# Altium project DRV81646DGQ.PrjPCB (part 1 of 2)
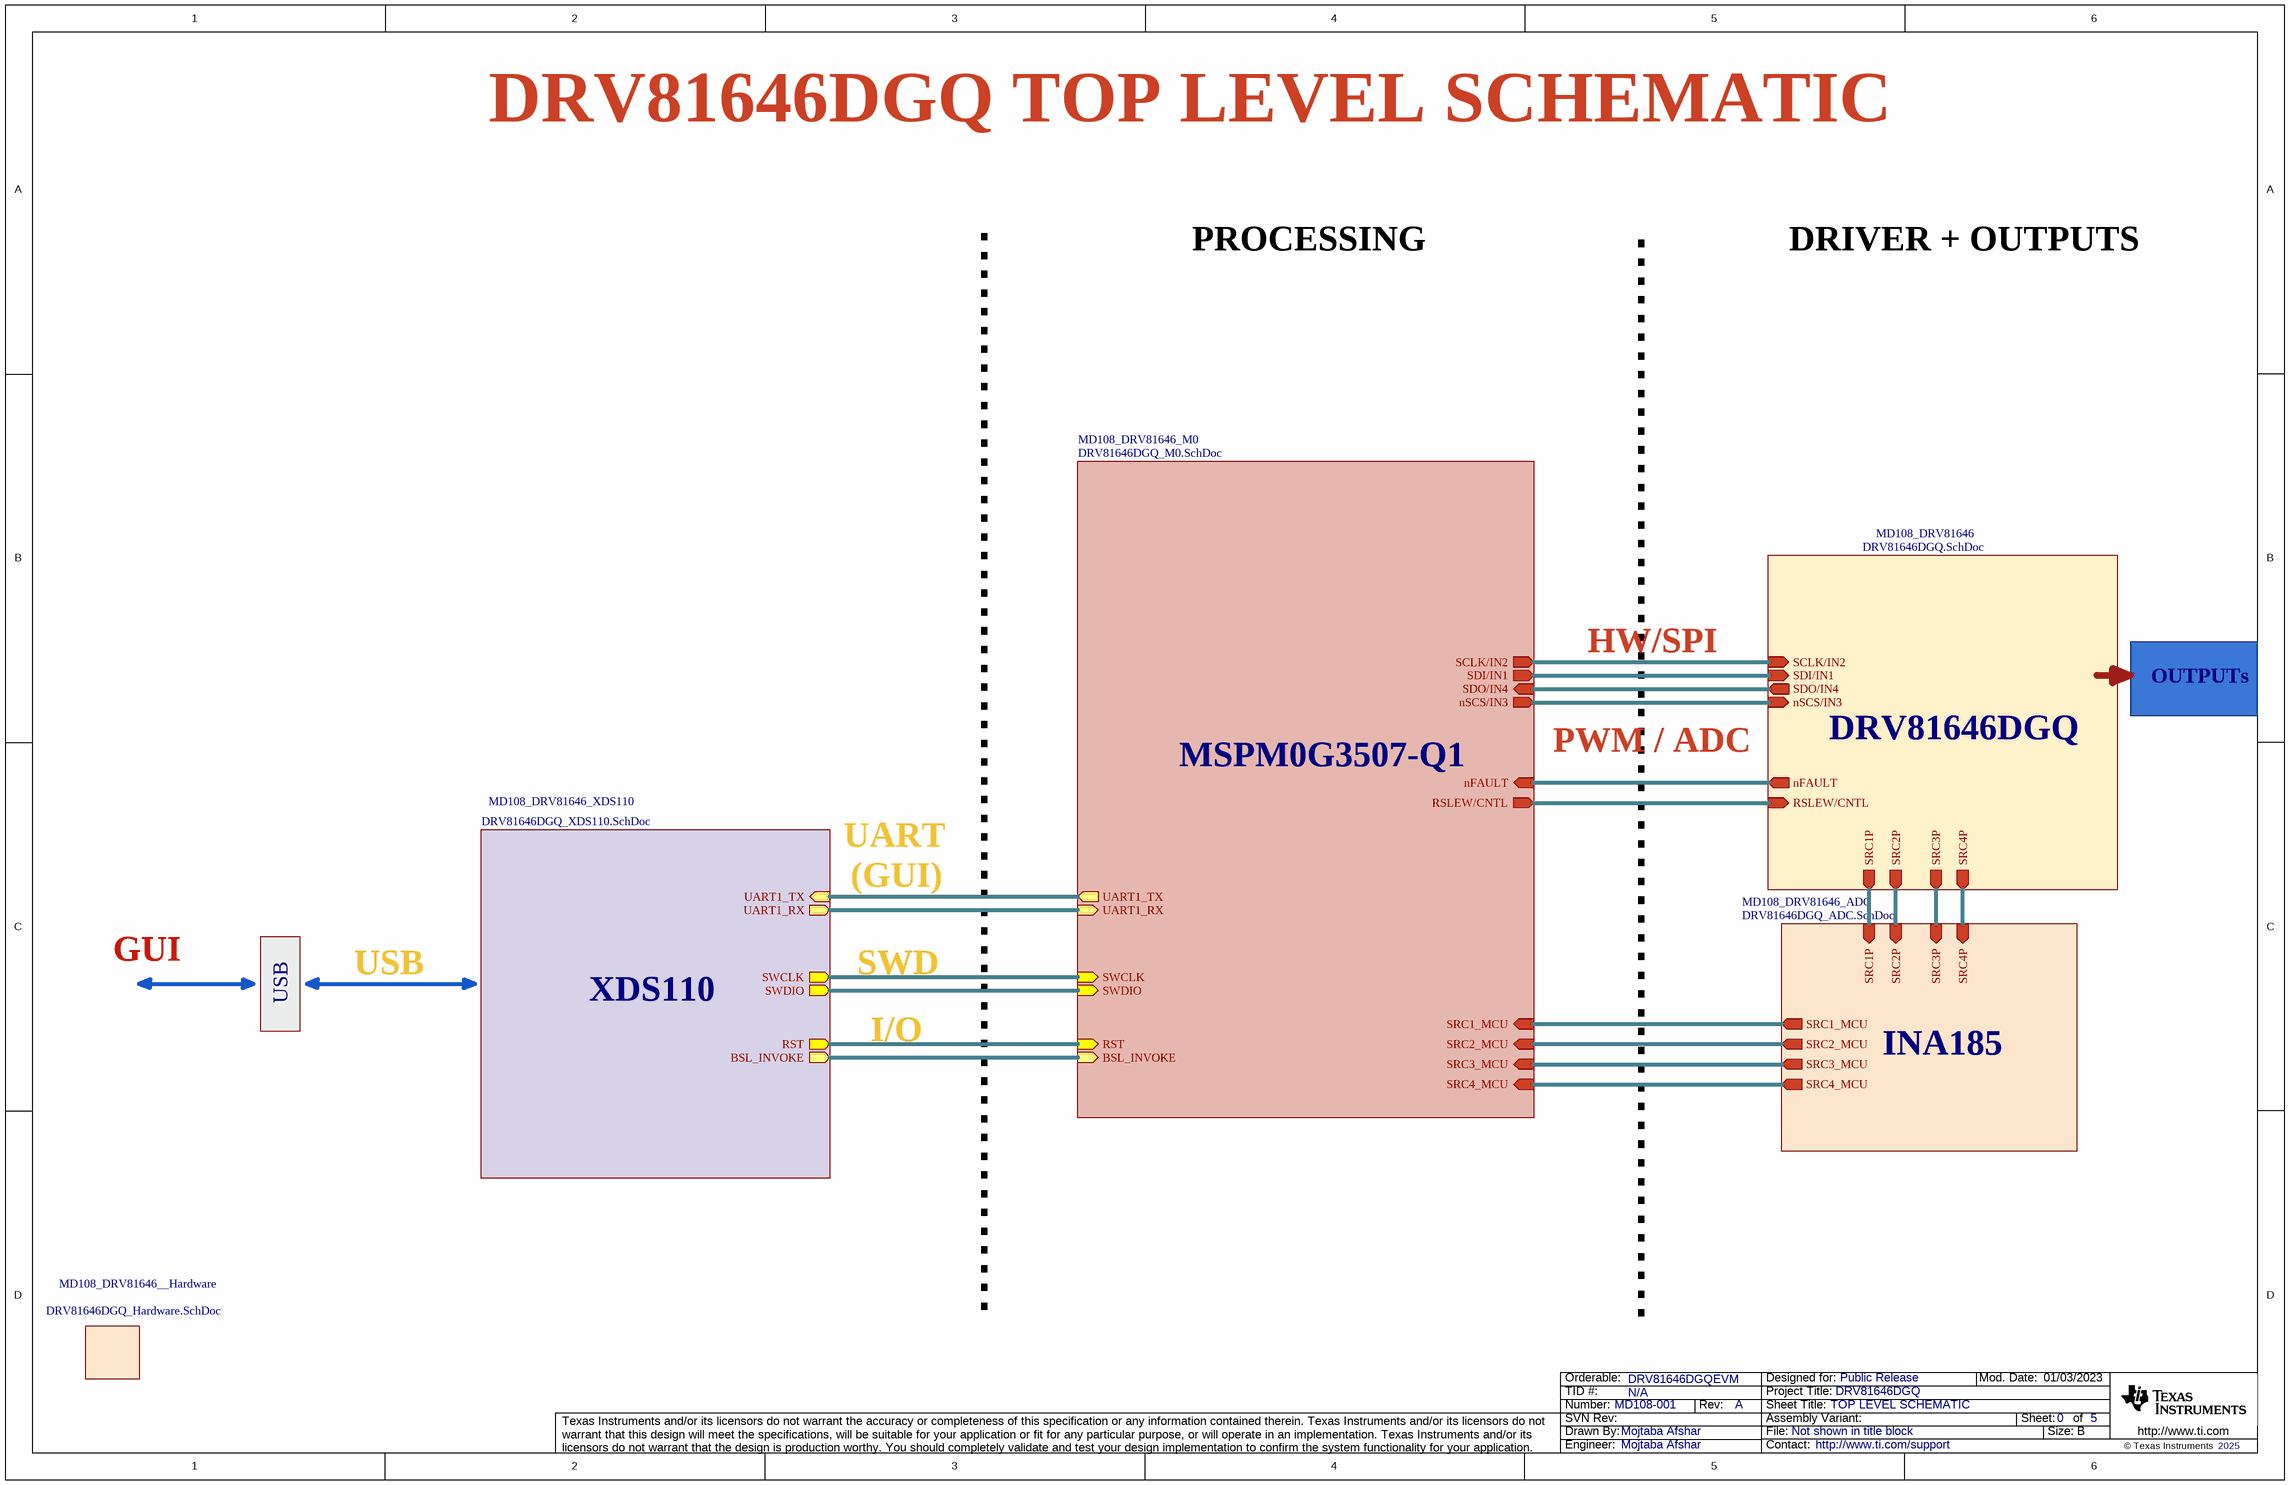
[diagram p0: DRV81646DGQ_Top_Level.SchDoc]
CopyrightYear: 2025; EVM_Orderable: DRV81646DGQEVM; PCB_Layout: Mojtaba Afshar; PCB_Rev: A; PRJ_Customer: Public Release; PRJ_Engineer: Mojtaba Afshar; PRJ_Number: MD108-001; PRJ_Title: DRV81646DGQ; SCH_Rev: A; TechSupport: http://www.ti.com/support; TID: N/A
6 sheets, 256 parts. Net scope: hierarchical (ports join the sheet entries above them; power ports are global).
Board file: MD108_DRV81646DGQ.PcbDoc
Sheets:
  DRV81646DGQ_Top_Level.SchDoc
    MD108_DRV81646__Hardware = DRV81646DGQ_Hardware.SchDoc
    MD108_DRV81646_XDS110 = DRV81646DGQ_XDS110.SchDoc
    MD108_DRV81646_M0 = DRV81646DGQ_M0.SchDoc
    MD108_DRV81646 = DRV81646DGQ.SchDoc
    MD108_DRV81646_ADC = DRV81646DGQ_ADC.SchDoc

## Sheet DRV81646DGQ_Top_Level.SchDoc: TOP LEVEL SCHEMATIC
size 431 x 279 mm; Date: Not shown in title block; ApprovedBy: Not shown in title block; CheckedBy: Not shown in title block; Author: Not shown in title block; CompanyName: Not shown in title block; DrawnBy: Mojtaba Afshar; Engineer: Not shown in title block; Organization: Not shown in title block; Address1: Not shown in title block; Address2: Not shown in title block; Address3: Not shown in title block; Address4: Not shown in title block; DocumentNumber: 2; Revision: Use project parameter SCH_Rev; SheetNumber: 0; SheetTotal: 5; PageSetup: Record=PageOptions¦CenterHorizontal=True¦CenterVertical=True¦PrintScale=1.00¦XCorrection=1.00¦YCorrection=1.00¦PrintKind=0¦BorderSize=5000000¦LeftOffset=0¦BottomOffset=0¦Orientation=2¦PaperLength=1000¦PaperWidth=1000¦Scale=100¦PaperSource=15¦PrintQuality=600¦MediaType=1¦DitherType=10¦PaperKind=Letter¦PrintScaleMode=1

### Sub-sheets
MD108_DRV81646 = DRV81646DGQ.SchDoc: nFAULT (out), SDI/IN1 (in), SDO/IN4 (out), SCLK/IN2 (in), nSCS/IN3 (in), RSLEW/CNTL (in), SRC1P (out), SRC2P (out), SRC3P (out), SRC4P (out)
MD108_DRV81646__Hardware = DRV81646DGQ_Hardware.SchDoc: no entries
MD108_DRV81646_ADC = DRV81646DGQ_ADC.SchDoc: SRC1P (in), SRC2P (in), SRC3P (in), SRC4P (in), SRC1_MCU (out), SRC2_MCU (out), SRC3_MCU (out), SRC4_MCU (out)
MD108_DRV81646_M0 = DRV81646DGQ_M0.SchDoc: SWDIO (in), SWCLK (in), nFAULT (in), SDI/IN1 (out), SDO/IN4 (in), SCLK/IN2 (out), RST (in), nSCS/IN3 (out), UART1_TX (out), UART1_RX (in), BSL_INVOKE (in), RSLEW/CNTL (out), SRC1_MCU (in), SRC2_MCU (in), SRC3_MCU (in), SRC4_MCU (in)
MD108_DRV81646_XDS110 = DRV81646DGQ_XDS110.SchDoc: SWDIO (out), SWCLK (out), RST (out), UART1_RX (out), UART1_TX (in), BSL_INVOKE (out)

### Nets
BSL_INVOKE: sheet MD108_DRV81646_XDS110/BSL_INVOKE, sheet MD108_DRV81646_M0/BSL_INVOKE
nFAULT: sheet MD108_DRV81646_M0/nFAULT, sheet MD108_DRV81646/nFAULT
nSCS/IN3: sheet MD108_DRV81646_M0/nSCS/IN3, sheet MD108_DRV81646/nSCS/IN3
RSLEW/CNTL: sheet MD108_DRV81646_M0/RSLEW/CNTL, sheet MD108_DRV81646/RSLEW/CNTL
RST: sheet MD108_DRV81646_XDS110/RST, sheet MD108_DRV81646_M0/RST
SCLK/IN2: sheet MD108_DRV81646_M0/SCLK/IN2, sheet MD108_DRV81646/SCLK/IN2
SDI/IN1: sheet MD108_DRV81646_M0/SDI/IN1, sheet MD108_DRV81646/SDI/IN1
SDO/IN4: sheet MD108_DRV81646_M0/SDO/IN4, sheet MD108_DRV81646/SDO/IN4
SRC1: sheet MD108_DRV81646/SRC1P, sheet MD108_DRV81646_ADC/SRC1P
SRC1_ADC_MCU: sheet MD108_DRV81646_M0/SRC1_MCU, sheet MD108_DRV81646_ADC/SRC1_MCU
SRC2: sheet MD108_DRV81646/SRC2P, sheet MD108_DRV81646_ADC/SRC2P
SRC2_ADC_MCU: sheet MD108_DRV81646_M0/SRC2_MCU, sheet MD108_DRV81646_ADC/SRC2_MCU
SRC3: sheet MD108_DRV81646/SRC3P, sheet MD108_DRV81646_ADC/SRC3P
SRC3_ADC_MCU: sheet MD108_DRV81646_M0/SRC3_MCU, sheet MD108_DRV81646_ADC/SRC3_MCU
SRC4: sheet MD108_DRV81646/SRC4P, sheet MD108_DRV81646_ADC/SRC4P
SRC4_ADC_MCU: sheet MD108_DRV81646_M0/SRC4_MCU, sheet MD108_DRV81646_ADC/SRC4_MCU
SWCLK: sheet MD108_DRV81646_XDS110/SWCLK, sheet MD108_DRV81646_M0/SWCLK
SWDIO: sheet MD108_DRV81646_XDS110/SWDIO, sheet MD108_DRV81646_M0/SWDIO
UART1_RX: sheet MD108_DRV81646_XDS110/UART1_RX, sheet MD108_DRV81646_M0/UART1_RX
UART1_TX: sheet MD108_DRV81646_XDS110/UART1_TX, sheet MD108_DRV81646_M0/UART1_TX

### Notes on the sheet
- DRV81646DGQ TOP LEVEL SCHEMATIC
- PROCESSING
- DRIVER + OUTPUTS
- HW/SPI
- OUTPUTs
- PWM / ADC
- DRV81646DGQ
- MSPM0G3507-Q1
- UART
- (GUI)
- GUI
- USB
- XDS110
- SWD
- I/O
- INA185

## Sheet DRV81646DGQ_Hardware.SchDoc: HARDWARE
size 431 x 279 mm; Date: Not shown in title block; ApprovedBy: Not shown in title block; CheckedBy: Not shown in title block; Author: Not shown in title block; CompanyName: Not shown in title block; DrawnBy: Mojtaba Afshar; Engineer: Not shown in title block; Organization: Not shown in title block; Address1: Not shown in title block; Address2: Not shown in title block; Address3: Not shown in title block; Address4: Not shown in title block; DocumentNumber: 3; Revision: Use project parameter SCH_Rev; SheetNumber: 5; SheetTotal: 5; PageSetup: Record=PageOptions¦CenterHorizontal=True¦CenterVertical=True¦PrintScale=1.00¦XCorrection=1.00¦YCorrection=1.00¦PrintKind=0¦BorderSize=5000000¦LeftOffset=0¦BottomOffset=0¦Orientation=2¦PaperLength=1000¦PaperWidth=1000¦Scale=100¦PaperSource=15¦PrintQuality=600¦MediaType=1¦DitherType=10¦PaperKind=Letter¦PrintScaleMode=1
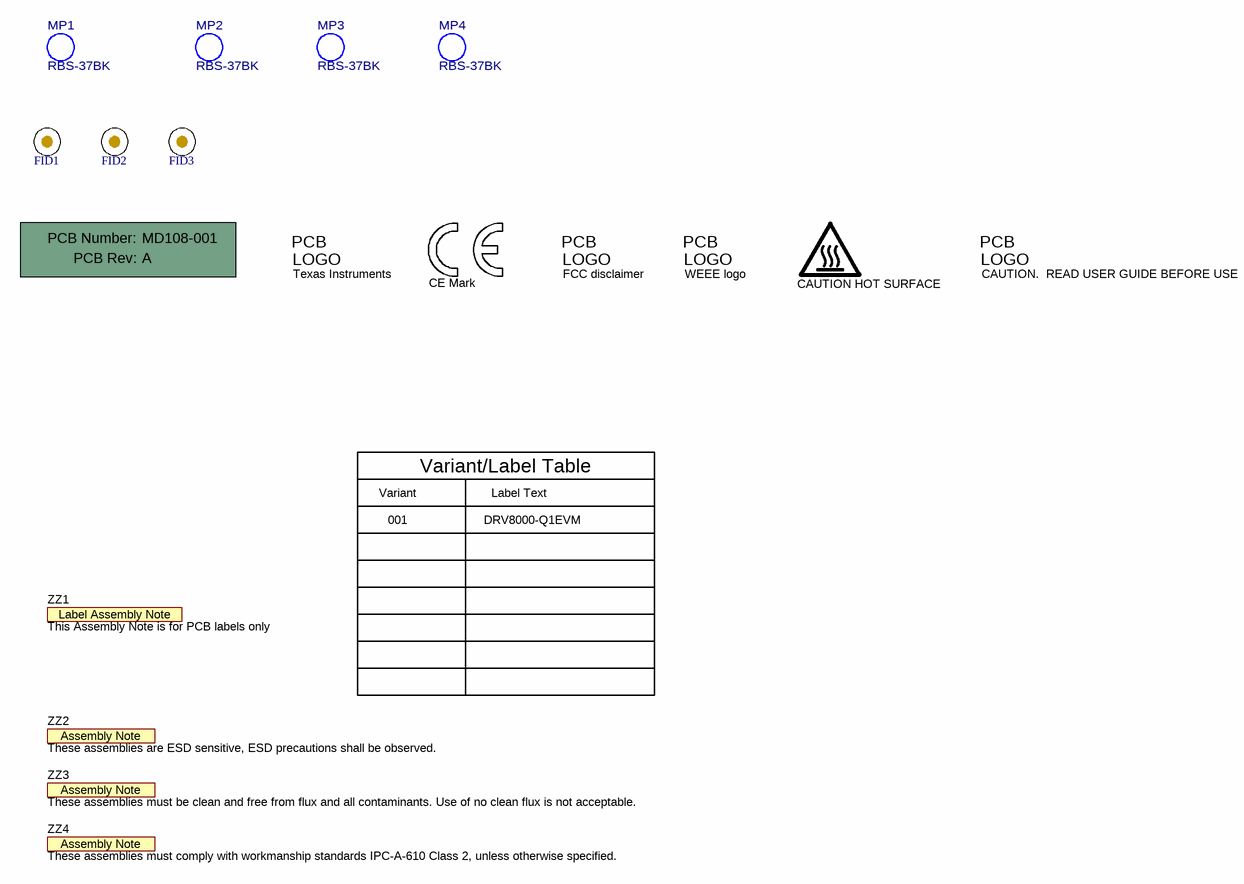
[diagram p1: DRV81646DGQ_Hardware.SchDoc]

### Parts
!PCB1  Printed Circuit Board  (value not drawn)  (mechanical)
FID1  Fiducial  [Fiducial10-20]  (value not drawn)
FID2  Fiducial  [Fiducial10-20]  (value not drawn)
FID3  Fiducial  [Fiducial10-20]  (value not drawn)
Logo1  CE Mark  [CE_Mark_5mm]  (no BOM)
Logo2  Texas Instruments  [TI_Stacked_Overlay_Small]  (no BOM)
Logo3  FCC disclaimer  [FCC_disclaimer]  (no BOM)
Logo4  WEEE logo  [WEEE_Minimum]  (no BOM)
LOGO5  CAUTION HOT SURFACE  [IEC_HotSurface_Small]  (no BOM)
Logo6  CAUTION.  READ USER GUIDE BEFORE USE  [IEC_Caution_Small]  (no BOM)
MP1  RBS-37BK  [FP-RBS-37BK_BUMPER_CYLI-MFG]
MP2  RBS-37BK  [FP-RBS-37BK_BUMPER_CYLI-MFG]
MP3  RBS-37BK  [FP-RBS-37BK_BUMPER_CYLI-MFG]
MP4  RBS-37BK  [FP-RBS-37BK_BUMPER_CYLI-MFG]
ZZ1  This Assembly Note is for PCB labels only  [AssemblyNoteLabel]  (no BOM)
ZZ2  These assemblies are ESD sensitive, ESD precautions shall be observed.  [AssemblyNote]  (no BOM)
ZZ3  These assemblies must be clean and free from flux and all contaminants. Use of no clean flux is not acceptable.  [AssemblyNote]  (no BOM)
ZZ4  These assemblies must comply with workmanship standards IPC-A-610 Class 2, unless otherwise specified.  [AssemblyNote]  (no BOM)

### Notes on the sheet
- Variant
- Variant/Label Table
- Label Text
- 001
- DRV8000-Q1EVM

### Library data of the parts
!PCB1 = CMP-0003618-2: Manufacturer: Any; PartNumber: MD108-001
FID1-FID3 = CMP-0077181-1: Fiducial mark.  There is nothing to buy or mount.
Logo1 = CMP-0074844-2: Manufacturer: Texas Instruments; SymbolCreator: a0412235; AEC Category: Q200; CompType: IC
Logo2 = CMP-0074838-1: Texas Instrument Corporate Signature; SymbolCreator: a0412235; Lib Reference: TI_Logo
Logo3 = CMP-0074847-1: FCC_disclaimer
Logo4 = CMP-0074769-4: Manufacturer: Texas Instruments; AEC Category: Q200; CompType: IC
LOGO5 = CMP-0074837-2: IEC 61010-1 Hot Surface Warning; Manufacturer: Texas Instruments; SymbolCreator: a0412235; CompType: IC; AEC Category: Q200
Logo6 = CMP-0074836-1: IEC 61010-1 Caution Warning; SymbolCreator: a0412235; Lib Reference: IEC_Caution
MP1-MP4 = CMP-0122650-1: Bumper Cylindrical, Dome 0.720" Dia (18.30mm) Polyurethane Black; Manufacturer: Essentra Components; AEC Qualified: No; SizeZ_mm: 14.7mm
ZZ1 = CMP-0003616-3
ZZ2 = CMP-0077236-1
ZZ3 = CMP-0077237-1
ZZ4 = CMP-0077238-1

## Sheet DRV81646DGQ_XDS110.SchDoc: XDS110
size 431 x 279 mm; Date: Not shown in title block; ApprovedBy: Not shown in title block; CheckedBy: Not shown in title block; Author: Not shown in title block; CompanyName: Not shown in title block; DrawnBy: Mojtaba Afshar; Engineer: Not shown in title block; Organization: Not shown in title block; Address1: Not shown in title block; Address2: Not shown in title block; Address3: Not shown in title block; Address4: Not shown in title block; DocumentNumber: 2; Revision: Use project parameter SCH_Rev; SheetNumber: 1; SheetTotal: 5; PageSetup: Record=PageOptions¦CenterHorizontal=True¦CenterVertical=True¦PrintScale=1.00¦XCorrection=1.00¦YCorrection=1.00¦PrintKind=0¦BorderSize=5000000¦LeftOffset=0¦BottomOffset=0¦Orientation=2¦PaperLength=1000¦PaperWidth=1000¦Scale=100¦PaperSource=15¦PrintQuality=600¦MediaType=1¦DitherType=10¦PaperKind=Letter¦PrintScaleMode=1
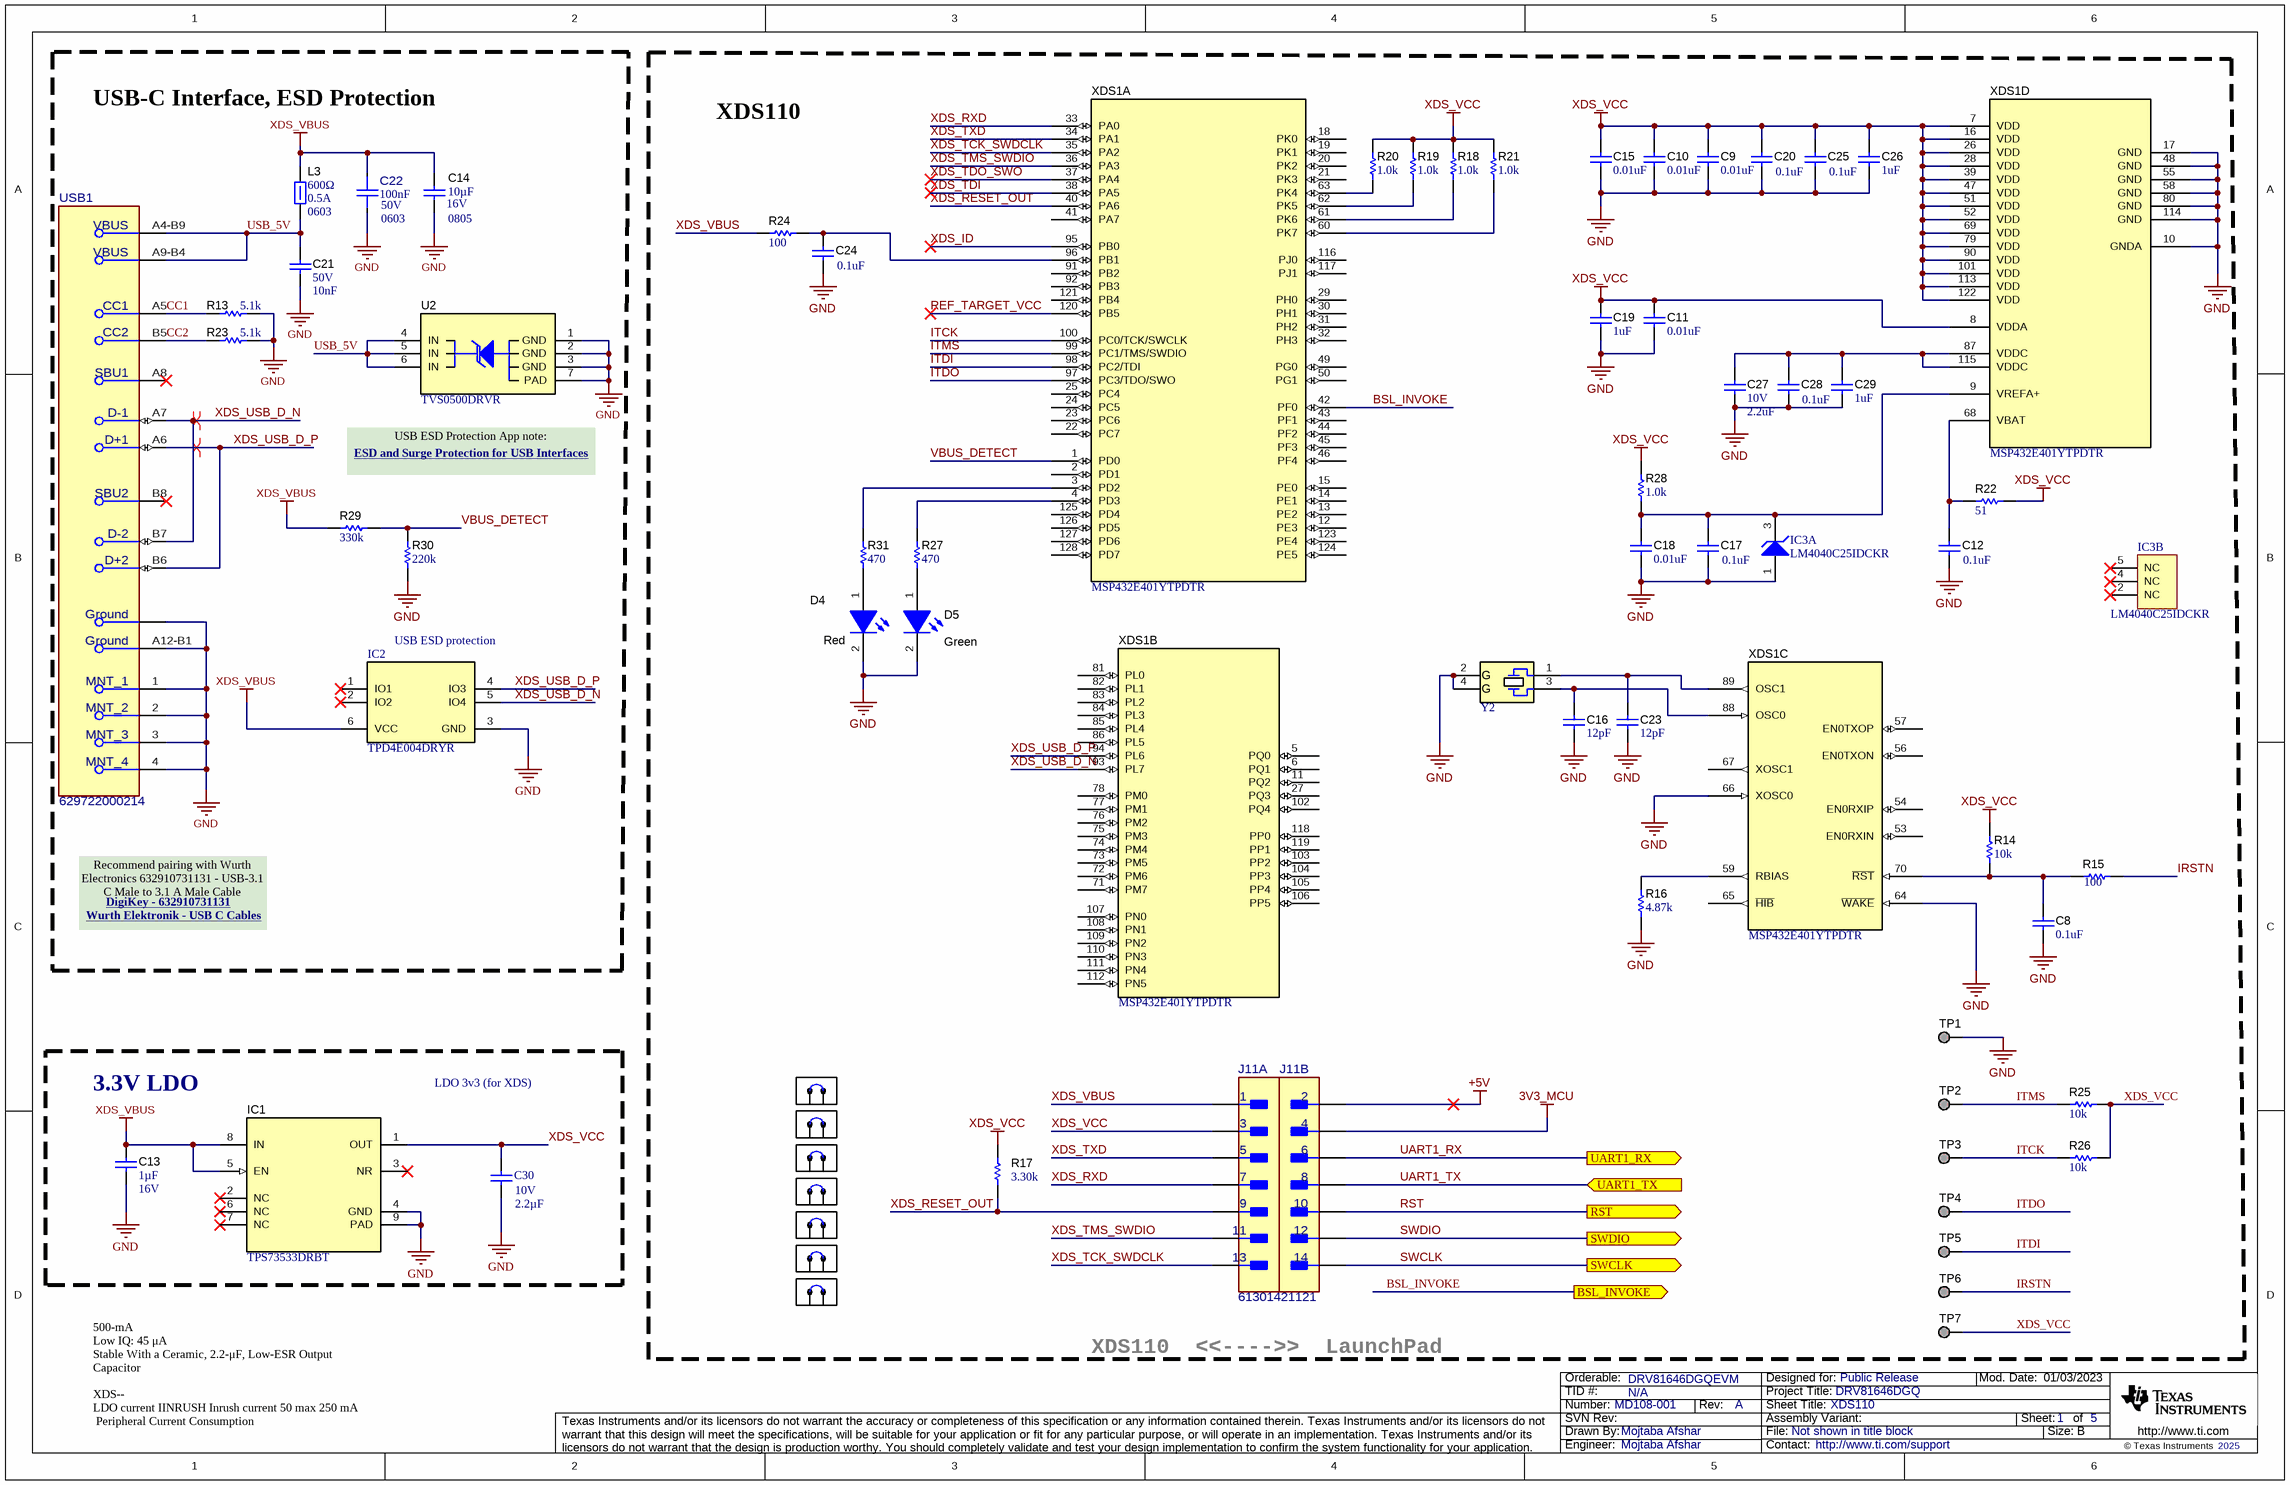
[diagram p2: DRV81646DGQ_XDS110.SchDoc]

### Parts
C8  ValueDisplayed: 0.1uF  [0402]  (hidden comment: GRM155R70J104KA01D)
C9  ValueDisplayed: 0.01uF  [0402]  (hidden comment: GRM155R71E103KA01D)
C10  ValueDisplayed: 0.01uF  [0402]  (hidden comment: GRM155R71E103KA01D)
C11  ValueDisplayed: 0.01uF  [0402]  (hidden comment: GRM155R71E103KA01D)
C12  ValueDisplayed: 0.1uF  [0402]  (hidden comment: GRM155R70J104KA01D)
C13  Cap_F: 1µF  VDC_V: 16V  [0603]  (hidden comment: 885012206052)
C14  PackageReference: 0805  VDC_V: 16V  ValueDisplayed: 10µF  [0805_150]  (hidden comment: 885012107014)
C15  ValueDisplayed: 0.01uF  [0402]  (hidden comment: GRM155R71E103KA01D)
C16  ValueDisplayed: 12pF  [0402]  (hidden comment: GRM1555C1H120JA01D)
C17  ValueDisplayed: 0.1uF  [0402]  (hidden comment: GRM155R70J104KA01D)
C18  ValueDisplayed: 0.01uF  [0402]  (hidden comment: GRM155R71E103KA01D)
C19  ValueDisplayed: 1uF  [0402]  (hidden comment: C1005X5R1E105K050BC)
C20  ValueDisplayed: 0.1uF  [0402]  (hidden comment: GRM155R70J104KA01D)
C21  VDC_V: 50V  Cap_F: 10nF  [0603]  (hidden comment: 885012206089)
C22  Cap_F: 100nF  PackageReference: 0603  VDC_V: 50V  [FP-885012206095_0603-MFG]  (hidden comment: 885012206095)
C23  ValueDisplayed: 12pF  [0402]  (hidden comment: GRM1555C1H120JA01D)
C24  ValueDisplayed: 0.1uF  [0402]  (hidden comment: GRM155R70J104KA01D)
C25  ValueDisplayed: 0.1uF  [0402]  (hidden comment: GRM155R70J104KA01D)
C26  ValueDisplayed: 1uF  [0402]  (hidden comment: C1005X5R1E105K050BC)
C27  VDC_V: 10V  ValueDisplayed: 2.2uF  [0603]  (hidden comment: C0603C225K8PACTU)
C28  ValueDisplayed: 0.1uF  [0402]  (hidden comment: GRM155R70J104KA01D)
C29  ValueDisplayed: 1uF  [0402]  (hidden comment: C1005X5R1E105K050BC)
C30  Cap_F: 2.2µF  Rated Voltage (DC): 10V  [WCAP-CSGP_0603_L1.6W0.8H0.8_Reflow]  (hidden comment: 885012206027)
D4  value Red  [LED_LTST-C190_Red]  (hidden comment: LTST-C190KRKT)
D5  value Green  [LED_LTST-C190]  (hidden comment: LTST-C190GKT)
IC1  TPS73533DRBT  [DRB0008A]
IC2  TPD4E004DRYR  [DRY0006A]
IC3  LM4040C25IDCKR  [DCK0005A_N]  (parts A,B of 2)
J11  61301421121  [FP-61301421121_HDR14-MFG]  (parts A,B of 2)
L3  Value2: 0.5A  ValueDisplayed: 600Ω  [0603]  (hidden comment: 742863160)
R13  ValueDisplayed: 5.1k  [0603]  (hidden comment: RC0603JR-075K1L)
R14  ValueDisplayed: 10k  [0402]  (hidden comment: CRCW040210K0JNED)
R15  ValueDisplayed: 100  [0402]  (hidden comment: CRCW0402100RJNED)
R16  ValueDisplayed: 4.87k  [0402]  (hidden comment: CRCW04024K87FKED)
R17  ValueDisplayed: 3.30k  [0402]  (hidden comment: ERJ-2RKF3301X)
R18  ValueDisplayed: 1.0k  [0402]  (hidden comment: CRCW04021K00JNED)
R19  ValueDisplayed: 1.0k  [0402]  (hidden comment: CRCW04021K00JNED)
R20  ValueDisplayed: 1.0k  [0402]  (hidden comment: CRCW04021K00JNED)
R21  ValueDisplayed: 1.0k  [0402]  (hidden comment: CRCW04021K00JNED)
R22  ValueDisplayed: 51  [0402]  (hidden comment: CRCW040251R0JNED)
R23  ValueDisplayed: 5.1k  [0603]  (hidden comment: RC0603JR-075K1L)
R24  ValueDisplayed: 100  [0402]  (hidden comment: CRCW0402100RJNED)
R25  ValueDisplayed: 10k  [0402]  (hidden comment: CRCW040210K0JNED)
R26  ValueDisplayed: 10k  [0402]  (hidden comment: CRCW040210K0JNED)
R27  ValueDisplayed: 470  [0402]  (hidden comment: CRCW0402470RJNED)
R28  ValueDisplayed: 1.0k  [0402]  (hidden comment: CRCW04021K00JNED)
R29  ValueDisplayed: 330k  [0402]  (hidden comment: RC0402FR-07330KL)
R30  ValueDisplayed: 220k  [0402]  (hidden comment: RC0402FR-07220KL)
R31  ValueDisplayed: 470  [0402]  (hidden comment: CRCW0402470RJNED)
SH-J14  60900213421  [Wurth_60900213421]  (value not drawn)
SH-J15  60900213421  [Wurth_60900213421]  (value not drawn)
SH-J16  60900213421  [Wurth_60900213421]  (value not drawn)
SH-J17  60900213421  [Wurth_60900213421]  (value not drawn)
SH-J18  60900213421  [Wurth_60900213421]  (value not drawn)
SH-J19  60900213421  [Wurth_60900213421]  (value not drawn)
SH-J20  60900213421  [Wurth_60900213421]  (value not drawn)
TP1  TESTPOINT  [TP_SM_1MM]  (value not drawn)  (no BOM)
TP2  TESTPOINT  [TP_SM_1MM]  (value not drawn)  (no BOM)
TP3  TESTPOINT  [TP_SM_1MM]  (value not drawn)  (no BOM)
TP4  TESTPOINT  [TP_SM_1MM]  (value not drawn)  (no BOM)
TP5  TESTPOINT  [TP_SM_1MM]  (value not drawn)  (no BOM)
TP6  TESTPOINT  [TP_SM_1MM]  (value not drawn)  (no BOM)
TP7  TESTPOINT  [TP_SM_1MM]  (value not drawn)  (no BOM)
U2  TVS0500DRVR  [DRV0006A]
USB1  629722000214  [FP-629722000214_CONN_USB-MFG]
XDS1  MSP432E401YTPDTR  [PDT0128A]  (parts A,B,C,D of 4)
Y2  NX3225GA-16.000M-STD-CRG-1  [NDK_NX3225GA]  (value not drawn)

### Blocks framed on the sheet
USB-C Interface, ESD Protection: C14 C21 C22 IC2 L3 R13 R23 R29 R30 U2 USB1
XDS110: C8-C12 C15-C20 C23-C29 D4 D5 IC3 J11 R14-R22 R24-R28 R31 SH-J14-SH-J20 TP1-TP7 XDS1 Y2
3.3V LDO: C13 C30 IC1

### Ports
BSL_INVOKE (out), RST (out), SWCLK (out), SWDIO (out), UART1_RX (out), UART1_TX (in)

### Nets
3V3_MCU: J11.4
+5V: J11.2
GND: C8.2 C9.2 C10.2 C11.2 C12.2 C13.2 C14.2 C15.2 C16.2 C17.2 C18.2 C19.2 C20.2 C21.2 C22.2 C23.2 C24.2 C25.2 C26.2 C27.2 C28.2 C29.2 C30.1 D4.2(K) D5.2(K) IC1.4(GND) IC1.9(PAD) IC2.3(GND) IC3.1(ANODE) R13.2 R16.1 R23.2 R30.1 TP1.1 U2.1(GND) U2.2(GND) U2.3(GND) U2.7(PAD) USB1.1(MNT_1) USB1.2(MNT_2) USB1.3(MNT_3) USB1.4(MNT_4) USB1.A1-B12(Ground) USB1.A12-B1(Ground) XDS1.10(GNDA) XDS1.17(GND) XDS1.48(GND) XDS1.55(GND) XDS1.58(GND) XDS1.64(~{WAKE}) XDS1.66(XOSC0) XDS1.80(GND) XDS1.114(GND) Y2.2(GND) Y2.4(GND)
XDS_VBUS: C13.1 C14.1 C22.1 IC1.5(EN) IC1.8(IN) IC2.6(VCC) J11.1 L3.2 R24.1 R29.1
XDS_VCC: C9.1 C10.1 C11.1 C15.1 C19.1 C20.1 C25.1 C26.1 C30.2 IC1.1(OUT) J11.3 R14.2 R17.2 R18.2 R19.2 R20.2 R21.2 R22.2 R25.1 R26.1 R28.2 TP7.1 XDS1.7(VDD) XDS1.8(VDDA) XDS1.16(VDD) XDS1.26(VDD) XDS1.28(VDD) XDS1.39(VDD) XDS1.47(VDD) XDS1.51(VDD) XDS1.52(VDD) XDS1.69(VDD) XDS1.79(VDD) XDS1.90(VDD) XDS1.101(VDD) XDS1.113(VDD) XDS1.122(VDD)
BSL_INVOKE: XDS1.42(PF0) ; port BSL_INVOKE
CC1: R13.1 USB1.A5(CC1)
CC2: R23.1 USB1.B5(CC2)
IRSTN: R15.1 TP6.1
ITCK: R26.2 TP3.1 XDS1.100(PC0/TCK/SWCLK)
ITDI: TP5.1 XDS1.98(PC2/TDI)
ITDO: TP4.1 XDS1.97(PC3/TDO/SWO)
ITMS: R25.2 TP2.1 XDS1.99(PC1/TMS/SWDIO)
REF_TARGET_VCC: XDS1.120(PB5)
RST: J11.10 ; port RST
SWCLK: J11.14 ; port SWCLK
SWDIO: J11.12 ; port SWDIO
UART1_RX: J11.6 ; port UART1_RX
UART1_TX: J11.8 ; port UART1_TX
USB_5V: C21.1 L3.1 U2.4(IN) U2.5(IN) U2.6(IN) USB1.A4-B9(VBUS) USB1.A9-B4(VBUS)
VBUS_DETECT: R29.2 R30.2 XDS1.1(PD0)
XDS_ID: XDS1.95(PB0)
XDS_RESET_OUT: J11.9 R17.1 XDS1.40(PA6)
XDS_RXD: J11.7 XDS1.33(PA0)
XDS_TCK_SWDCLK: J11.13 XDS1.35(PA2)
XDS_TDI: XDS1.38(PA5)
XDS_TDO_SWO: XDS1.37(PA4)
XDS_TMS_SWDIO: J11.11 XDS1.36(PA3)
XDS_TXD: J11.5 XDS1.34(PA1)
XDS_USB_D_N: IC2.5(IO4) USB1.A7(D-1) USB1.B7(D-2) XDS1.93(PL7)
XDS_USB_D_P: IC2.4(IO3) USB1.A6(D+1) USB1.B6(D+2) XDS1.94(PL6)
NetC8_1: C8.1 R14.1 R15.2 XDS1.70(~{RST})
NetC12_1: C12.1 R22.1 XDS1.68(VBAT)
NetC16_1: C16.1 XDS1.88(OSC0) Y2.3
NetC17_1: C17.1 C18.1 IC3.3(CATHODE) R28.1 XDS1.9(VREFA+)
NetC23_1: C23.1 XDS1.89(OSC1) Y2.1
NetC24_1: C24.1 R24.2 XDS1.96(PB1)
NetC27_1: C27.1 C28.1 C29.1 XDS1.87(VDDC) XDS1.115(VDDC)
NetD4_1: D4.1(A) R31.1
NetD5_1: D5.1(A) R27.1
NetR16_2: R16.2 XDS1.59(RBIAS)
NetR18_1: R18.1 XDS1.61(PK6)
NetR19_1: R19.1 XDS1.62(PK5)
NetR20_1: R20.1 XDS1.63(PK4)
NetR21_1: R21.1 XDS1.60(PK7)
NetR27_2: R27.2 XDS1.4(PD3)
NetR31_2: R31.2 XDS1.3(PD2)

Not connected (* = marked no-connect by the designer): IC1 2(NC)* 3(NR)* 6(NC)* 7(NC)*; IC2 1(IO1)* 2(IO2)*; IC3 2(NC)* 4(NC)* 5(NC)*; USB1 A8(SBU1)* B8(SBU2)*; XDS1 2(PD1) 5(PQ0) 6(PQ1) 11(PQ2) 12(PE3) 13(PE2) 14(PE1) 15(PE0) 18(PK0) 19(PK1) 20(PK2) 21(PK3) 22(PC7) 23(PC6) 24(PC5) 25(PC4) 27(PQ3) 29(PH0) 30(PH1) 31(PH2) 32(PH3) 41(PA7) 43(PF1) 44(PF2) 45(PF3) 46(PF4) 49(PG0) 50(PG1) 53(EN0RXIN) 54(EN0RXIP) 56(EN0TXON) 57(EN0TXOP) 65(~{HIB}) 67(XOSC1) 71(PM7) 72(PM6) 73(PM5) 74(PM4) 75(PM3) 76(PM2) 77(PM1) 78(PM0) 81(PL0) 82(PL1) 83(PL2) 84(PL3) 85(PL4) 86(PL5) 91(PB2) 92(PB3) 102(PQ4) 103(PP2) 104(PP3) 105(PP4) 106(PP5) 107(PN0) 108(PN1) 109(PN2) 110(PN3) 111(PN4) 112(PN5) 116(PJ0) 117(PJ1) 118(PP0) 119(PP1) 121(PB4) 123(PE4) 124(PE5) 125(PD4) 126(PD5) 127(PD6) 128(PD7)

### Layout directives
differential pair: XDS_USB_D_N, XDS_USB_D_P

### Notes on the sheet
- USB ESD Protection App note:
- ESD and Surge Protection for USB Interfaces <https://www.ti.com/lit/an/slvaf82b/slvaf82b.pdf>
- (near IC2) USB ESD protection
- Recommend pairing with Wurth Electronics 632910731131 - USB-3.1 C Male to 3.1 A Male Cable
- Wurth Elektronik - USB C Cables <https://www.we-online.com/en/components/products/COM_3_1_CAB_ASSEMBLIES>
- DigiKey - 632910731131 <https://www.digikey.com/en/products/detail/w%C3%BCrth-elektronik/632910731131/5723517>
- LDO 3v3 (for XDS)
- XDS110  <<---->>  LaunchPad
- 500-mA
  Low IQ: 45 μA
  Stable With a Ceramic, 2.2-μF, Low-ESR Output
  Capacitor
  XDS--
  LDO current IINRUSH Inrush current 50 max 250 mA
  Peripheral Current Consumption
  M0 IVDD 100 mA
  m0IVss 100 mA
  m0 I IO 60 mA
  LEDs with 470 takes 3.5 maA
  IDDUSB 4mA
  IDDEMAC 2 mA
  IDDEMACPHY 30mA

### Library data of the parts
C8 C12 C17 C20 C24 C25 C28 = CMP-0006623-2: CAP, CERM, 0.1 uF, 6.3 V, +/- 10%, X7R, 0402; Manufacturer: MuRata; TaMin_C: -55°C; Polarized: N; SizeAreaWB_mm2: 3; Value1: Unknown; U/M: EA; Value: 0.1uF; TaMax_C: 125°C; SizeZ_mm: 0.6; SizeX_mm: 1; SizeY_mm: 0.5; Value2: 6.3V; Cap_F: 100nF; AEC Category: Q200
C9-C11 C15 C18 = CMP-0006658-2: CAP, CERM, 0.01 uF, 25 V, +/- 10%, X7R, 0402; Manufacturer: MuRata; TaMin_C: -55°C; Polarized: N; SizeAreaWB_mm2: 3; Value1: Unknown; U/M: EA; Value: 0.01uF; TaMax_C: 125°C; SizeZ_mm: 0.6; SizeX_mm: 1; SizeY_mm: 0.5; Value2: 25V; Cap_F: 10nF; AEC Category: Q200
C13 = CMP-0006831-4: CAP, CERM, 1 uF, 16 V, +/- 10%, X7R, 0603; Manufacturer: Wurth Elektronik; TaMin_C: -55°C; Polarized: N; SizeAreaWB_mm2: 4.68; Value1: Unknown; U/M: EA; Value: 1uF; TaMax_C: 125°C; SizeZ_mm: 1; SizeX_mm: 1.6; SizeY_mm: 0.8; SizeArea_mm2: 1.28; AEC Category: Q200
C14 = CMP-0078154-1: CAP, CERM, 10 µF, 16 V,+/- 20%, X5R, 0805; Manufacturer: Wurth Elektronik; TaMin_C: -55°C; Polarized: N; SizeAreaWB_mm2: 6.75; U/M: EA; Value: 10uF; TaMax_C: 85°C; SizeZ_mm: 1.5; SizeX_mm: 2; SizeY_mm: 1.25; SizeArea_mm2: 2.5; AEC Category: Q200
C16 C23 = CMP-0006415-2: CAP, CERM, 12 pF, 50 V, +/- 5%, C0G/NP0, 0402; Manufacturer: MuRata; TaMin_C: -55°C; Polarized: N; SizeAreaWB_mm2: 3; Value1: Unknown; U/M: EA; Value: 12pF; TaMax_C: 125°C; SizeZ_mm: 0.6; SizeX_mm: 1; SizeY_mm: 0.5; Value2: 50V; AEC Category: Q200
C19 C26 C29 = CMP-0006276-2: CAP, CERM, 1 uF, 25 V, +/- 10%, X5R, 0402; Manufacturer: TDK; TaMin_C: -55°C; Polarized: N; SizeAreaWB_mm2: 3; Value1: Unknown; U/M: EA; Value: 1uF; TaMax_C: 80°C; SizeZ_mm: 0.6; SizeX_mm: 1; SizeY_mm: 0.5; Value2: 25V; Cap_F: 1µF; AEC Category: Q200
C21 = CMP-0750039-1: CAP, CERM, 0.01 µF, 50 V,+/- 10%, X7R, 0603; Manufacturer: Wurth Elektronik; Polarized: N; AEC Category: Q200; TaMax_C: 125°C; SizeAreaWB_mm2: 4.68; Value: 0.01uF; SizeArea_mm2: 1.28; SizeY_mm: 0.8; SizeZ_mm: 1; ValueDisplayed: 0.01µF; SizeX_mm: 1.6; U/M: EA; TaMin_C: -55°C
C22 = CMP-0049204-1: 0.1 µF ±10% 50V Ceramic Capacitor X7R 0603 (1608 Metric); Manufacturer: Wurth; AEC Qualified: No; SizeZ_mm: 0.87mm; TempCo: 15%; Value: 100nF
C27 = CMP-0006906-5: CAP, CERM, 2.2 uF, 10 V, +/- 10%, X5R, 0603; Manufacturer: Kemet; TaMin_C: -55°C; Polarized: N; SizeAreaWB_mm2: 4.68; Value1: Unknown; U/M: EA; Value: 2.2uF; TaMax_C: 85°C; SizeZ_mm: 1; SizeX_mm: 1.6; SizeY_mm: 0.8; SizeArea_mm2: 1.28; Cap_F: 2.2µF; AEC Category: Q200
C30 = CMP-0119330-1: WCAP-CSGP Multilayer Ceramic Chip Capacitor, General Purpose, size 0603, X7R, 2.2µF, 10VDC; Manufacturer: Wurth Elektronik; Capacitance Tolerance: +/-10%; Case/Size Code: 0603; Dissipation Factor: 10%; Insulation Resistance: 0.02GOhm; Technical Reference: X7R0603225K010DFCT10000
D4 = CMP-0078131-2: LED, Red, SMD; Manufacturer: Lite-On; Type: AlInGaP; Ir_A: 10µA; Angle: 130; Power_TotalModule: 62.5mW; Value2: 2V; Green_Lifecycle: Not Set; Io_A: 20mA; Value1: .0625W; Green_REACh: Incomplete; Vr_V: 5V
D5 = CMP-0002827-3: LED, Green, SMD; Manufacturer: Lite-On; Power_TotalModule: 100mW; Value2: 2.1V; Io_A: 20mA; Value1: 0.1W
IC1 = CMP-0036329-3: 500mA, Adjustable, Low Quiescent Current, Low-Noise, High-PSRR, Single-Output LDO Regulator, DRB0008A (VSON-8); Manufacturer: Texas Instruments; AEC Category: Q200; Vout Adj(Max)(V): 3.3; Vdo(Typ)(mV): 280; SizeY_mm: 3.0; Vin(Max)(V): 6.5; Accuracy(%): 2; Vin(Min)(V): 2.7; SizeAreaWB_mm2: 16.0; SizeZ_mm: 1.0; AEC Qualified: N; SizeArea_mm2: 9.0; Iout(Max)(A): 0.5; Rating: Catalog; Iq(Typ)(mA): 0.04; CompType: IC
IC2 = CMP-0043115-3: 4-Channel ESD Protection Array for High-Speed Data Interfaces, DRY0006A (USON-6); Manufacturer: Texas Instruments; IO Leakage Current(nA): 1; USB High Speed: TRUE; IO Capacitance(Typ)(pF): 1.6; Eco-Plan: Green (RoHS & no Sb/Br); IEC 61000-4-2 Contact(+/- kV): 8; Breakdown Voltage(Min)(V): 6; IEC 61000-4-2 Air-Gap(+/- kV): 12; AEC Category: Q200; AEC Qualified: N; CompType: IC; Rating: Catalog; SizeArea_mm2: 1.45; SizeAreaWB_mm2: 4.9; SizeX_mm: 1.0; SizeZ_mm: 0.6
IC3 = CMP-0032790-2: Precision Micropower Shunt Voltage Reference, 0.5% accuracy, 2.5 V, 15 ppm / degC, 15 mA, -40 to 85 degC, 5-pin SC70 (DCK), Green (RoHS & no Sb/Br); Manufacturer: Texas Instruments; Min Iz for Regulation(uA): 75; Temp Coeff(Max)(ppm/ degree C): 100; VO(V): 2.5; Temp Coeff(Typ)(ppm/ degree C): 15; Rating: Catalog; Initial Accuracy @ 25/deg C(%): 0.5; AEC Category: Q200; AEC Qualified: N; CompType: IC; SizeAreaWB_mm2: 9.3; SizeArea_mm2: 4.2; SizeX_mm: 2.1; SizeY_mm: 2.0; SizeZ_mm: 1.1
J11 = CMP-0097334-1: Connector Header Through Hole 14 position 0.100" (2.54mm); Manufacturer: Wurth Electronics; AEC Qualified: No; Conn Gender: Male; Current_A: 3A; Voltage_V: 250V; ContactFinish: Gold; Row_Count: 2; SizeZ_mm: 8.89mm; Conn Orientation: Straight
L3 = CMP-0003267-2: Ferrite Bead, 600 ohm @ 100 MHz, 0.5 A, 0603; Manufacturer: Wurth Elektronik; Ztyp@1GHz_Ohm: 997.006; ZTyp@100MHz_Ohm: 600; SizeAreaWB_mm2: 4.68; DCR_ohm: 3.5d; Value1: 0.35 ohm; Value: 600 ohm; Imax_A: 5dA; SizeZ_mm: 1; SizeX_mm: 1.6; SizeY_mm: 0.8; SizeArea_mm2: 1.28
R13 R23 = CMP-0025932-5: RES, 5.1 k, 5%, 0.1 W, 0603; Manufacturer: Yageo; Power_W: 100mW; TempCo: 100 ppm/C; Value_Code: 5k10; Value: 5.1k; EIA_Code: E24; SizeX_mm: 1.6; SizeY_mm: 0.8; SizeZ_mm: 1; Value2: 0.1W; SizeArea_mm2: 1.28; AEC Qualified: N; VDC_V: 75V; AEC Category: Q200; SizeAreaWB_mm2: 4.68
R14 R25 R26 = CMP-0026825-5: RES, 10 k, 5%, 0.063 W, AEC-Q200 Grade 0, 0402; Manufacturer: Vishay-Dale; Power_W: 63mW; TempCo: 200 ppm/C; Value_Code: 10k0; Value: 10k; EIA_Code: E24; SizeX_mm: 1; SizeY_mm: 0.5; SizeZ_mm: 0.6; Value2: 0.063W; AEC Qualified: Y; VDC_V: 50V; AEC Category: Q200; AEC Grade: 0
R15 R24 = CMP-0026824-3: RES, 100, 5%, 0.063 W, AEC-Q200 Grade 0, 0402; Manufacturer: Vishay-Dale; Power_W: 63mW; TempCo: 200 ppm/C; Value_Code: 100R; Value: 100; EIA_Code: E24; SizeX_mm: 1; SizeY_mm: 0.5; SizeZ_mm: 0.6; Value2: 0.063W; AEC Qualified: Y; VDC_V: 50V; AEC Category: Q200; AEC Grade: 0
R16 = CMP-0026413-2: RES, 4.87 k, 1%, 0.063 W, AEC-Q200 Grade 0, 0402; Manufacturer: Vishay-Dale; Power_W: 63mW; TempCo: 100 ppm/C; Value_Code: 4k87; Value: 4.87k; EIA_Code: E96; SizeX_mm: 1; SizeY_mm: 0.5; SizeZ_mm: 0.6; Value2: 0.063W; AEC Qualified: Y; VDC_V: 50V; AEC Category: Q200; AEC Grade: 0
R17 = CMP-0026695-1: RES, 3.30 k, 1%, 0.1 W, AEC-Q200 Grade 0, 0402; Manufacturer: Panasonic; Power_W: 100mW; TempCo: 100 ppm/C; Value_Code: 3k30; U/M: EA; Value: 3.30k; Res_ohm: 3.3k; SizeX_mm: 1; SizeY_mm: 0.5; SizeZ_mm: 0.6; Value2: 0.1W; AEC Qualified: Y; VDC_V: 50V; AEC Grade: 0; AEC Category: Q200
R18-R21 R28 = CMP-0026852-3: RES, 1.0 k, 5%, 0.063 W, AEC-Q200 Grade 0, 0402; Manufacturer: Vishay-Dale; Power_W: 63mW; TempCo: 200 ppm/C; Value_Code: 1k00; Value: 1.0k; EIA_Code: E24; Res_ohm: 1k; SizeX_mm: 1; SizeY_mm: 0.5; SizeZ_mm: 0.6; Value2: 0.063W; AEC Qualified: Y; VDC_V: 50V; AEC Category: Q200; AEC Grade: 0
R22 = CMP-0026946-3: RES, 51, 5%, 0.063 W, AEC-Q200 Grade 0, 0402; Manufacturer: Vishay-Dale; Power_W: 63mW; TempCo: 200 ppm/C; Value_Code: 51R0; Value: 51; EIA_Code: E24; SizeX_mm: 1; SizeY_mm: 0.5; SizeZ_mm: 0.6; Value2: 0.063W; AEC Qualified: Y; VDC_V: 50V; AEC Category: Q200; AEC Grade: 0
R27 R31 = CMP-0026934-3: RES, 470, 5%, 0.063 W, AEC-Q200 Grade 0, 0402; Manufacturer: Vishay-Dale; Power_W: 63mW; TempCo: 200 ppm/C; Value_Code: 470R; Value: 470; EIA_Code: E24; SizeX_mm: 1; SizeY_mm: 0.5; SizeZ_mm: 0.6; Value2: 0.063W; AEC Qualified: Y; VDC_V: 50V; AEC Category: Q200; AEC Grade: 0
R29 = CMP-0026731-1: RES, 330 k, 1%, 0.0625 W, 0402; Manufacturer: Yageo America; Power_W: 62.5mW; TempCo: 100 ppm/C; U/M: EA; Value: 330k; SizeX_mm: 1; SizeY_mm: 0.5; SizeZ_mm: 0.6; AEC Qualified: N; VDC_V: 50V; AEC Category: Q200
R30 = CMP-0026728-1: RES, 220 k, 1%, 0.0625 W, 0402; Manufacturer: Yageo America; Power_W: 62.5mW; TempCo: 100 ppm/C; U/M: EA; Value: 220k; SizeX_mm: 1; SizeY_mm: 0.5; SizeZ_mm: 0.6; AEC Qualified: N; VDC_V: 50V; AEC Category: Q200
SH-J14-SH-J20 = CMP-0003761-2: Shunt, 2.54mm, Gold, Black; Manufacturer: Wurth Elektronik
TP1-TP7 = CMP-0003825-1: 1mm Test Point, SMT; Manufacturer: Any
U2 = CMP-0077837-1: 5-V Precision Surge Protection Clamp, DRV0006A (WSON-6); Alternate Manufacturer: Texas Instruments; SizeAreaWB_mm2: 9.0; SizeZ_mm: 0.8; SizeX_mm: 2.0; SizeArea_mm2: 4.0; CompType: IC; AEC Qualified: N; AEC Category: Q200
USB1 = CMP-0095999-2: Conenctor USB 2.0 Type C Horizontal SMT; Manufacturer: Wurth Electronics; Current_A: 5A; ContactFinish: Gold,Nickel; AEC Qualified: No; Shrouded: true; Voltage_V: 20V; SizeZ_mm: 3.51mm; Usb Standard: USB 2.0; Is Female: yes
XDS1 = CMP-0077954-1: MSP432E401YTPDT, PDT0128A (TQFP-128); Alternate Manufacturer: Texas Instruments; SizeAreaWB_mm2: 324; SizeZ_mm: 1.2; SizeX_mm: 16; SizeArea_mm2: 256; CompType: IC; AEC Qualified: N; AEC Category: Q200
Y2 = CMP-0004635-3: Crystal, 16 MHz, 8pF, SMD; Manufacturer: NDK; TaMax_C: 70°C; TaMin_C: -10°C; Frequency Stability: +/-30ppm; Frequency_Fixed: 16MHz

## Sheet DRV81646DGQ_M0.SchDoc: MSPM0G3507-Q1
size 431 x 279 mm; Date: Not shown in title block; ApprovedBy: Not shown in title block; CheckedBy: Not shown in title block; Author: Not shown in title block; CompanyName: Not shown in title block; DrawnBy: Mojtaba Afshar; Engineer: Not shown in title block; Organization: Not shown in title block; Address1: Not shown in title block; Address2: Not shown in title block; Address3: Not shown in title block; Address4: Not shown in title block; DocumentNumber: 1; Revision: Use project parameter SCH_Rev; SheetNumber: 2; SheetTotal: 5; PageSetup: Record=PageOptions¦CenterHorizontal=True¦CenterVertical=True¦PrintScale=1.00¦XCorrection=1.00¦YCorrection=1.00¦PrintKind=0¦BorderSize=5000000¦LeftOffset=0¦BottomOffset=0¦Orientation=2¦PaperLength=1000¦PaperWidth=1000¦Scale=100¦PaperSource=15¦PrintQuality=600¦MediaType=1¦DitherType=10¦PaperKind=Letter¦PrintScaleMode=1
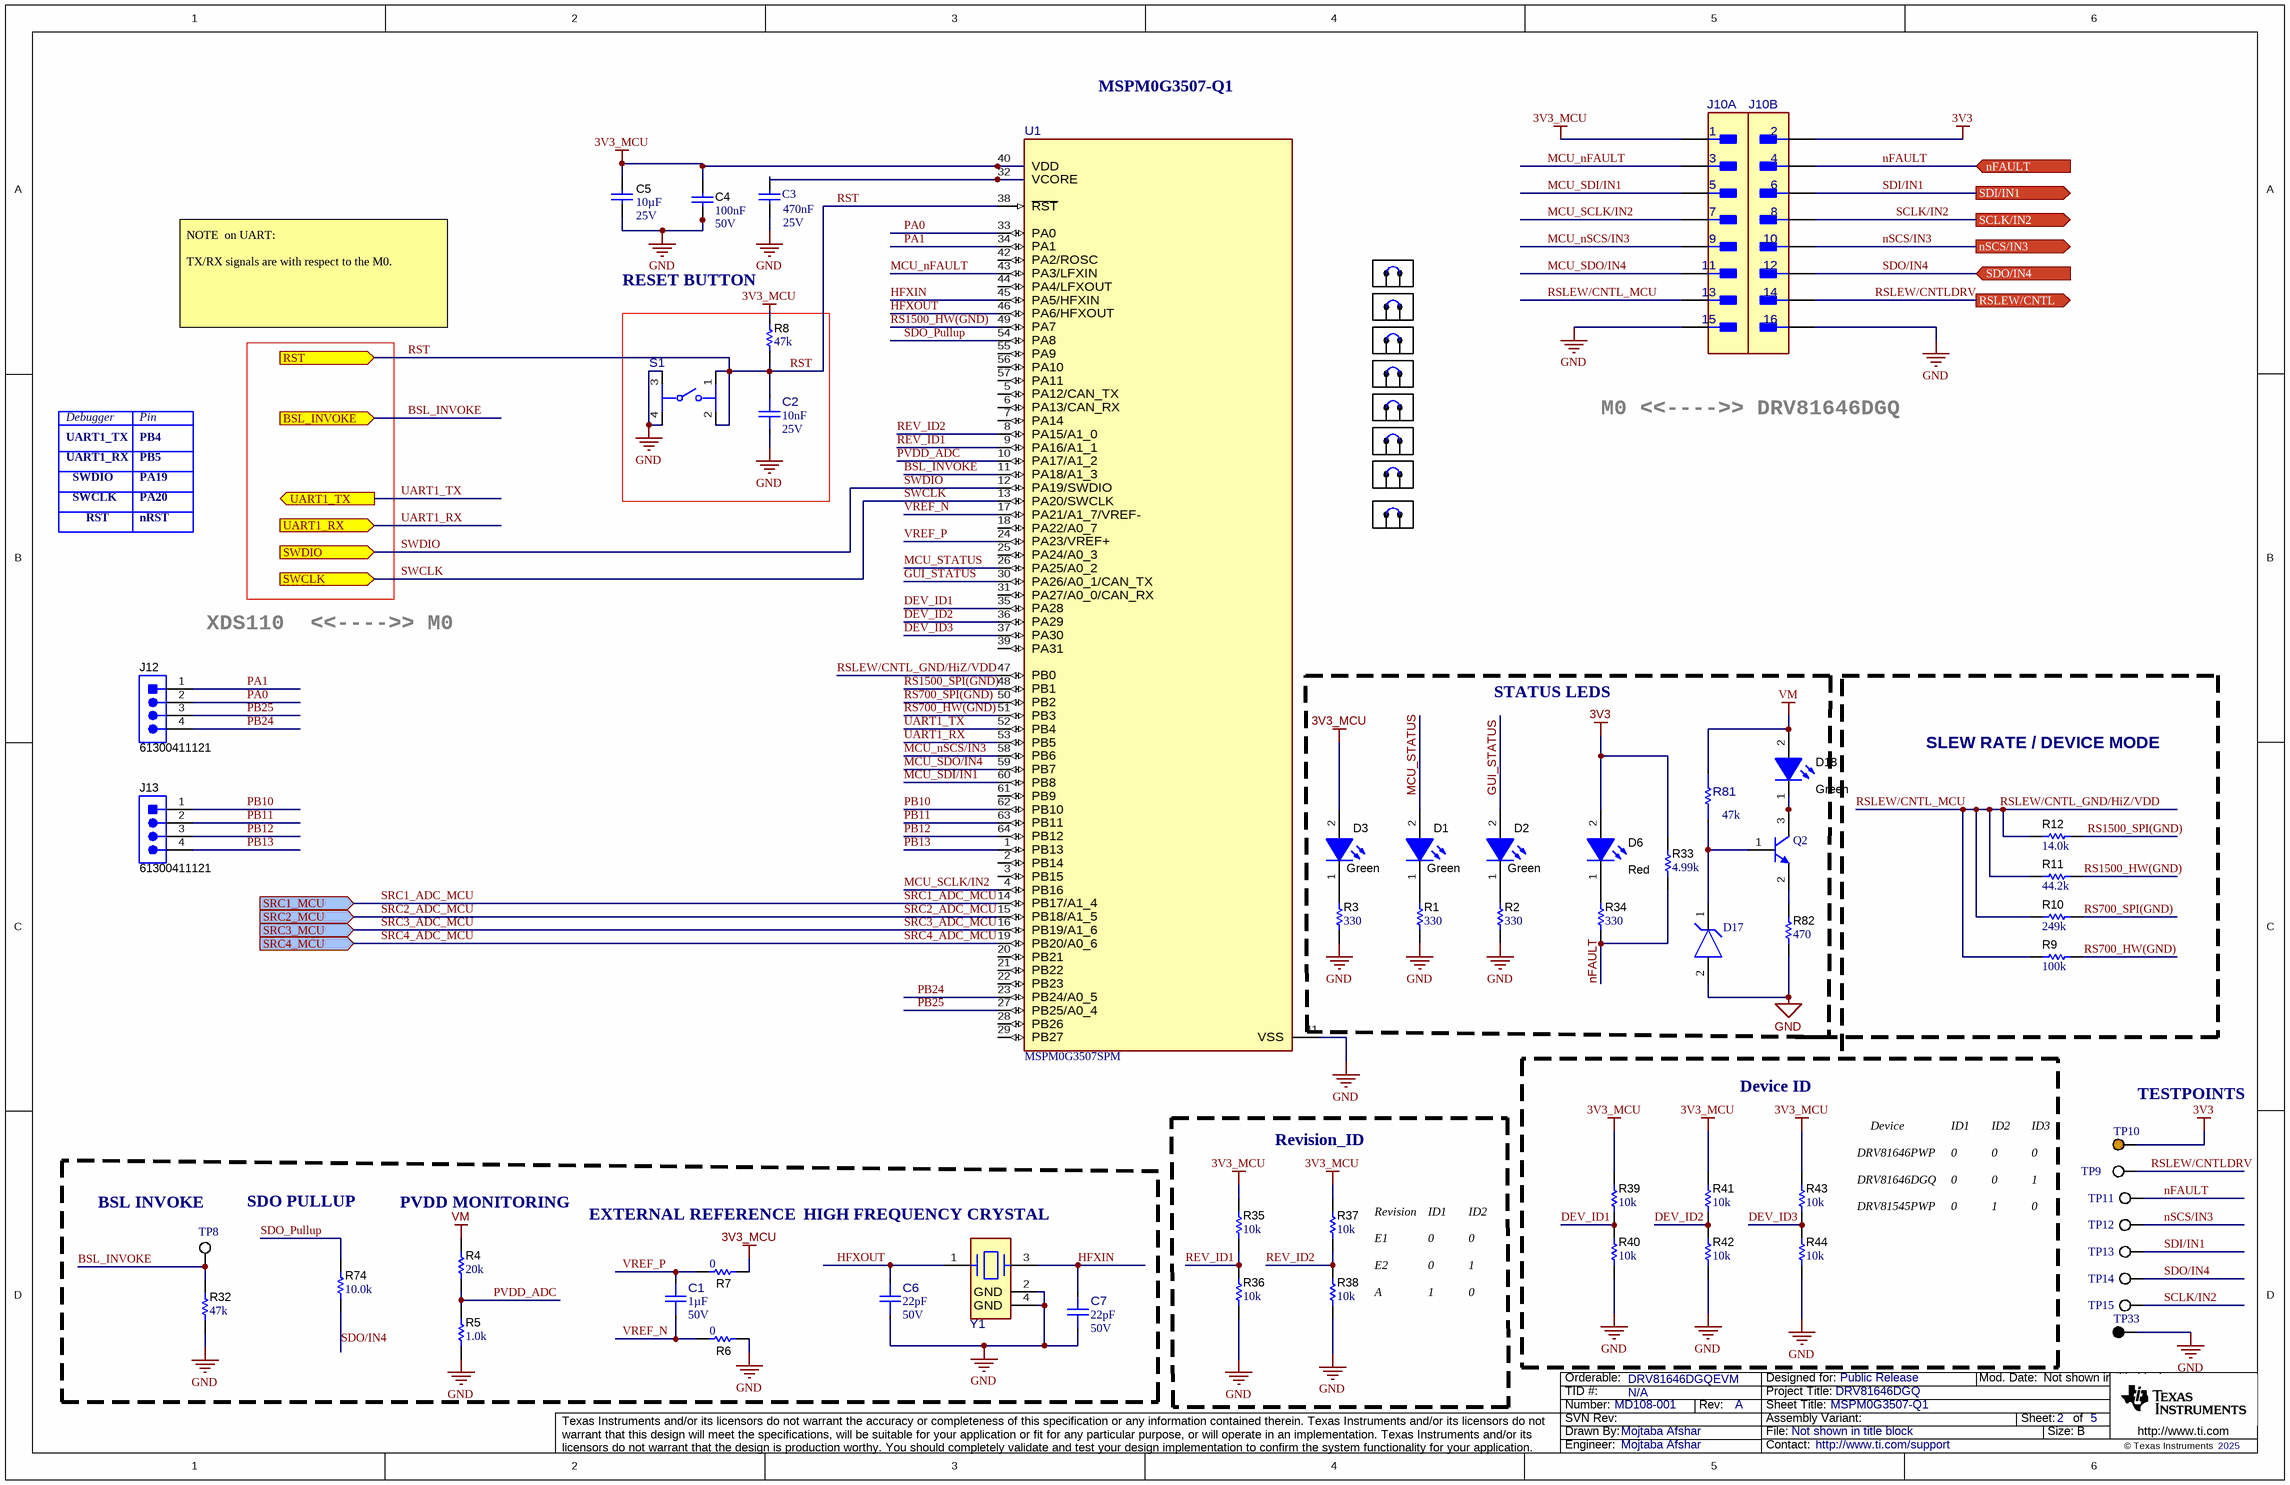
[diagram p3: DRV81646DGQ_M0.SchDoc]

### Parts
C1  Cap_F: 1µF  VDC_V: 50V  [FP-885012206126_0603-MFG]  (hidden comment: 885012206126)
C2  Cap_F: 10nF  VDC_V: 25V  [FP-885012206065_0603-MFG]  (hidden comment: 885012206065)
C3  value 470nF  Rated Voltage (DC): 25V  [WCAP-CSGP_0603_L1.6W0.8H0.8_Reflow]  (hidden comment: 885012206075R)
C4  Cap_F: 100nF  VDC_V: 50V  [0603]  (hidden comment: 885012206095)
C5  Cap_F: 10µF  VDC_V: 25V  [0603]  (hidden comment: GRM188R61E106KA73D)
C6  ValueDisplayed: 22pF  VDC_V: 50V  [FP-885012005057_0402-MFG]  (hidden comment: 885012005057)
C7  ValueDisplayed: 22pF  VDC_V: 50V  [FP-885012005057_0402-MFG]  (hidden comment: 885012005057)
D1  value Green  [WL-SMCW_GREEN]  (hidden comment: 150060VS75000)
D2  value Green  [WL-SMCW_GREEN]  (hidden comment: 150060VS75000)
D3  value Green  [WL-SMCW_GREEN]  (hidden comment: 150060VS75000)
D6  value Red  [WL-SMCW_RED]  (hidden comment: 150060RS75000)
D17  BZX84J-B4V7,115  [FP-SOD323F-MFG]  (value not drawn)
D18  value Green  [WL-SMCW_GREEN]  (hidden comment: 150060VS75000)
J10  61301621121  [FP-61301621121_HDR16-MFG]  (value not drawn)  (parts A,B of 2)
J12  61300411121  [WURTH_61300411121]
J13  61300411121  [WURTH_61300411121]
Q2  BC846BLT1G  [ONSC-SOT-23-3-318-08_V]  (value not drawn)
R1  ValueDisplayed: 330  [0603]  (hidden comment: RC0603JR-07330RL)
R2  ValueDisplayed: 330  [0603]  (hidden comment: RC0603JR-07330RL)
R3  ValueDisplayed: 330  [0603]  (hidden comment: RC0603JR-07330RL)
R4  ValueDisplayed: 20k  [1210]  (hidden comment: RC1210JR-0720KL)
R5  ValueDisplayed: 1.0k  [0603]  (hidden comment: RC0603JR-071KL)
R6  value 0  [0603]  (hidden comment: Resistor)
R7  value 0  [0603]  (hidden comment: Resistor)
R8  ValueDisplayed: 47k  [0402]  (hidden comment: CRCW040247K0JNED)
R9  ValueDisplayed: 100k  [0603]  (hidden comment: ERJ-3GEYJ104V)
R10  ValueDisplayed: 249k  [0603]  (hidden comment: RC0603FR-07249KL)
R11  ValueDisplayed: 44.2k  [0603]  (hidden comment: RC0603FR-0744K2L)
R12  ValueDisplayed: 14.0k  [0603]  (hidden comment: RC0603FR-0714KL)
R32  ValueDisplayed: 47k  [0402]  (hidden comment: CRCW040247K0JNED)
R33  ValueDisplayed: 4.99k  [0603]  (hidden comment: RC0603FR-074K99L)
R34  ValueDisplayed: 330  [0603]  (hidden comment: RC0603JR-07330RL)
R35  ValueDisplayed: 10k  [0603L]  (hidden comment: RC0603JR-0710KL)
R36  ValueDisplayed: 10k  [0603L]  (hidden comment: RC0603JR-0710KL)
R37  ValueDisplayed: 10k  [0603L]  (hidden comment: RC0603JR-0710KL)
R38  ValueDisplayed: 10k  [0603L]  (hidden comment: RC0603JR-0710KL)
R39  ValueDisplayed: 10k  [0603L]  (hidden comment: RC0603JR-0710KL)
R40  ValueDisplayed: 10k  [0603L]  (hidden comment: RC0603JR-0710KL)
R41  ValueDisplayed: 10k  [0603L]  (hidden comment: RC0603JR-0710KL)
R42  ValueDisplayed: 10k  [0603L]  (hidden comment: RC0603JR-0710KL)
R43  ValueDisplayed: 10k  [0603L]  (hidden comment: RC0603JR-0710KL)
R44  ValueDisplayed: 10k  [0603L]  (hidden comment: RC0603JR-0710KL)
R74  ValueDisplayed: 10.0k  [0603]  (hidden comment: RC0603FR-0710KL)
R81  value 47k  [FP-RCC040247K0FKED_0402-MFG]  (hidden comment: RCC040247K0FKED)
R82  ValueDisplayed: 470  [0603]  (hidden comment: RC0603FR-07470RL)
S1  430481025816  [FP-430481025816_SMT_SW_6MM2_6MM2-MFG]  (value not drawn)
SH-J2  60900213421  [Wurth_60900213421]  (value not drawn)
SH-J3  60900213421  [Wurth_60900213421]  (value not drawn)
SH-J4  60900213421  [Wurth_60900213421]  (value not drawn)
SH-J5  60900213421  [Wurth_60900213421]  (value not drawn)
SH-J6  60900213421  [Wurth_60900213421]  (value not drawn)
SH-J7  60900213421  [Wurth_60900213421]  (value not drawn)
SH-J8  60900213421  [Wurth_60900213421]  (value not drawn)
SH-J9  60900213421  [Wurth_60900213421]  (value not drawn)
TP8  5002  [Keystone5002]  (value not drawn)
TP9  5012  [Keystone5012]  (value not drawn)
TP10  5013  [Keystone5013]  (value not drawn)
TP11  5012  [Keystone5012]  (value not drawn)
TP12  5012  [Keystone5012]  (value not drawn)
TP13  5012  [Keystone5012]  (value not drawn)
TP14  5012  [Keystone5012]  (value not drawn)
TP15  5012  [Keystone5012]  (value not drawn)
TP33  5011  [Keystone5011]  (value not drawn)
U1  MSPM0G3507SPM  [PM0064A-MFG]
Y1  X1E0000210179  [FP-X1E0000210179_TSX-3225-MFG]  (value not drawn)

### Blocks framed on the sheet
STATUS LEDS: D1-D3 D6 D17 D18 Q2 R1-R3 R33 R34 R81 R82
Revision_ID: R35-R38

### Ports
BSL_INVOKE (in), nFAULT (in), nSCS/IN3 (out), RSLEW/CNTL (out), RST (in), SCLK/IN2 (out), SDI/IN1 (out), SDO/IN4 (in), SRC1_MCU (in), SRC2_MCU (in), SRC3_MCU (in), SRC4_MCU (in), SWCLK (in), SWDIO (in), UART1_RX (in), UART1_TX (out)

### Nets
3V3: D6.2(A) J10.2 R33.2 TP10.1
3V3_MCU: C4.1 C5.1 D3.2(A) J10.1 R7.1 R8.2 R35.1 R37.1 R39.1 R41.1 R43.1 U1.40(VDD)
GND: C2.2 C3.1 C4.2 C5.2 C6.1 C7.1 D17.2(A) J10.15 J10.16 R1.1 R2.1 R3.1 R5.1 R6.1 R32.1 R36.2 R38.2 R40.2 R42.2 R44.2 R82.1 S1.3 S1.4 TP33.1 U1.41(VSS) Y1.2(GND) Y1.4(GND)
VM: D18.2(A) R4.2 R81.2
BSL_INVOKE: R32.2 TP8.1 U1.11(PA18/A1_3) ; port BSL_INVOKE
DEV_ID1: R39.2 R40.1 U1.35(PA28)
DEV_ID2: R41.2 R42.1 U1.36(PA29)
DEV_ID3: R43.2 R44.1 U1.37(PA30)
GUI_STATUS: D2.2(A) U1.30(PA26/A0_1/CAN_TX)
HFXIN: C7.2 U1.45(PA5/HFXIN) Y1.3
HFXOUT: C6.2 U1.46(PA6/HFXOUT) Y1.1
MCU_nFAULT: J10.3 U1.43(PA3/LFXIN)
MCU_nSCS/IN3: J10.9 U1.58(PB6)
MCU_SCLK/IN2: J10.7 U1.4(PB16)
MCU_SDI/IN1: J10.5 U1.60(PB8)
MCU_SDO/IN4: J10.11 U1.59(PB7)
MCU_STATUS: D1.2(A) U1.26(PA25/A0_2)
nFAULT: J10.4 R33.1 R34.1 TP11.1 ; port nFAULT
nSCS/IN3: J10.10 TP12.1 ; port nSCS/IN3
PA0: J12.2 U1.33(PA0)
PA1: J12.1 U1.34(PA1)
PB10: J13.1 U1.62(PB10)
PB11: J13.2 U1.63(PB11)
PB12: J13.3 U1.64(PB12)
PB13: J13.4 U1.1(PB13)
PB24: J12.4 U1.23(PB24/A0_5)
PB25: J12.3 U1.27(PB25/A0_4)
PVDD_ADC: R4.1 R5.2 U1.10(PA17/A1_2)
REV_ID1: R35.2 R36.1 U1.9(PA16/A1_1)
REV_ID2: R37.2 R38.1 U1.8(PA15/A1_0)
RS700_HW(GND): R9.1 U1.51(PB3)
RS700_SPI(GND): R10.1 U1.50(PB2)
RS1500_HW(GND): R11.1 U1.49(PA7)
RS1500_SPI(GND): R12.1 U1.48(PB1)
RSLEW/CNTL_GND/HiZ/VDD: J10.13 R9.2 R10.2 R11.2 R12.2 U1.47(PB0)  [also labelled RSLEW/CNTL_MCU]
RSLEW/CNTLDRV: J10.14 TP9.1 ; port RSLEW/CNTL  [project net RSLEW/CNTL]
RST: C2.1 R8.1 S1.1 S1.2 U1.38(~{RST}) ; port RST
SCLK/IN2: J10.8 TP15.1 ; port SCLK/IN2
SDI/IN1: J10.6 TP13.1 ; port SDI/IN1
SDO/IN4: J10.12 R74.1 TP14.1 ; port SDO/IN4
SDO_Pullup: R74.2 U1.54(PA8)
SRC1_ADC_MCU: U1.14(PB17/A1_4) ; port SRC1_MCU
SRC2_ADC_MCU: U1.15(PB18/A1_5) ; port SRC2_MCU
SRC3_ADC_MCU: U1.16(PB19/A1_6) ; port SRC3_MCU
SRC4_ADC_MCU: U1.19(PB20/A0_6) ; port SRC4_MCU
SWCLK: U1.13(PA20/SWCLK) ; port SWCLK
SWDIO: U1.12(PA19/SWDIO) ; port SWDIO
UART1_RX: U1.53(PB5) ; port UART1_RX
UART1_TX: U1.52(PB4) ; port UART1_TX
VREF_N: C1.1 R6.2 U1.17(PA21/A1_7/VREF-)
VREF_P: C1.2 R7.2 U1.24(PA23/VREF+)
NetC3_2: C3.2 U1.32(VCORE)
NetD1_1: D1.1(K) R1.2
NetD2_1: D2.1(K) R2.2
NetD3_1: D3.1(K) R3.2
NetD6_1: D6.1(K) R34.2
NetD17_1: D17.1(C) Q2.1(B) R81.1
NetD18_1: D18.1(K) Q2.3(C)
NetQ2_2: Q2.2(E) R82.2

Not connected (* = marked no-connect by the designer): U1 2(PB14) 3(PB15) 5(PA12/CAN_TX) 6(PA13/CAN_RX) 7(PA14) 18(PA22/A0_7) 20(PB21) 21(PB22) 22(PB23) 25(PA24/A0_3) 28(PB26) 29(PB27) 31(PA27/A0_0/CAN_RX) 39(PA31) 42(PA2/ROSC) 44(PA4/LFXOUT) 55(PA9) 56(PA10) 57(PA11) 61(PB9)

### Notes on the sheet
- MSPM0G3507-Q1
- RESET BUTTON
- NOTE  on UART:
  TX/RX signals are with respect to the M0.
- Debugger
- Pin
- M0 <<---->> DRV81646DGQ
- UART1_TX
- UART1_RX
- SWDIO
- SWCLK
- PA19
- PA20
- PB4
- PB5
- RST
- nRST
- XDS110  <<---->> M0
- SLEW RATE / DEVICE MODE
- Device ID
- (near TP10) TESTPOINTS
- DRV81646PWP
- Device
- ID1
- 0
- ID2
- ID3
- (near TP8) BSL INVOKE
- SDO PULLUP
- (near R4) PVDD MONITORING
- EXTERNAL REFERENCE
- HIGH FREQUENCY CRYSTAL
- (near R37) Revision
- DRV81646DGQ
- DRV81545PWP
- 1
- E1
- A
- E2

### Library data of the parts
C1 = CMP-0120896-1: 1 µF ±10% 50V Ceramic Capacitor X7R 0603 (1608 Metric); Manufacturer: Wurth Electronics; AEC Qualified: No; SizeZ_mm: 0.95mm; TempCo: 15%; ValueDisplayed: 1uF; Value: 1µF
C2 = CMP-0120893-1: 10000 pF ±10% 25V Ceramic Capacitor X7R 0603 (1608 Metric); Manufacturer: Wurth Electronics; AEC Qualified: No; SizeZ_mm: 0.87mm; TempCo: 15%; Value: 10nF
C3 = CMP-0119380-1: WCAP-CSGP Multilayer Ceramic Chip Capacitor, General Purpose, size 0603, X7R Class II, 470nF, 25VDC; Manufacturer: Wurth Elektronik; Capacitance Tolerance: +/-10%; Case/Size Code: 0603; Dissipation Factor: 10%; Insulation Resistance: 1.1GOhm; Technical Reference: X7R0603474K025DFCT20000
C4 = CMP-0006837-4: CAP, CERM, 0.1 uF, 50 V, +/- 10%, X7R, 0603; Manufacturer: Wurth Elektronik; TaMin_C: -55°C; Polarized: N; SizeAreaWB_mm2: 4.68; Value1: Unknown; U/M: EA; Value: 0.1uF; TaMax_C: 125°C; SizeZ_mm: 1; SizeX_mm: 1.6; SizeY_mm: 0.8; SizeArea_mm2: 1.28; AEC Category: Q200
C5 = CMP-0860569-1: CAP, CERM, 10 µF, 25 V,+/- 10%, X5R, 0603; Manufacturer: MuRata; TaMin_C: -55°C; Polarized: N; SizeAreaWB_mm2: 4.68; U/M: EA; Value: 10uF; TaMax_C: 85°C; SizeZ_mm: 1; SizeX_mm: 1.6; SizeY_mm: 0.8; SizeArea_mm2: 1.28; AEC Category: Q200
C6 C7 = CMP-0120892-1: 22 pF ±5% 50V Ceramic Capacitor C0G, NP0 0402 (1005 Metric); Manufacturer: Wurth Electronics; AEC Qualified: No; SizeZ_mm: 0.55mm; TempCo: 30ppm/°C; Value: 22pF
D1-D3 D18 = CMP-0002894-2: LED, Green, SMD; Manufacturer: Wurth Elektronik; Type: AlInGaP; Value2: 2V; Io_A: 20mA; Value1: W
D6 = CMP-0002947-3: LED, Red, SMD; Manufacturer: Wurth Elektronik; Value1: 0.072W; Vf_V: 2V; Angle: 140; Tjmax_C: 85°C; Type: AlInGaP; Vr_V: 5V; Io_A: 30mA; Power_TotalModule: 72mW
D17 = CMP-14400-000003-2: DIODE ZENER 4.7V 550MW SOD323F
J10 = CMP-0125672-1: Connector Header Through Hole 16 position 0.100" (2.54mm); Manufacturer: Wurth; ContactFinish: Gold; Current_A: 3A; Row_Count: 2; Voltage_V: 250V; AEC Qualified: No; Conn Gender: Male; Conn Orientation: Straight; SizeZ_mm: 8.89mm
J12 J13 = CMP-0054798-2: Header, 2.54 mm, 4x1, Gold, TH; Manufacturer: Wurth Elektronik; Pitch_mm: 2.54; Gender: Male; Row_Count: 1; Cert_UL: Y; Shrouded: N
Q2 = CMP-1048-00779-1: General Purpose Transistor, NPN Silicon, 3-Pin SOT-23, Pb-Free, Tape and Reel; Manufacturer: On Semiconductor; fT Min (MHz): 100; IC Continuous (A): 0.1
R1-R3 R34 = CMP-0025912-5: RES, 330, 5%, 0.1 W, 0603; Manufacturer: Yageo; Power_W: 100mW; TempCo: 100 ppm/C; Value_Code: 330R; Value: 330; EIA_Code: E24; SizeX_mm: 1.6; SizeY_mm: 0.8; SizeZ_mm: 1; Value2: 0.1W; SizeArea_mm2: 1.28; AEC Qualified: N; VDC_V: 75V; AEC Category: Q200; SizeAreaWB_mm2: 4.68
R4 = CMP-0083496-1: RES, 20 k, 5%, 0.5 W, 1210; Manufacturer: Yageo; Power_W: 500mW; TempCo: 100 ppm/C; SizeAreaWB_mm2: 14.7; Value_Code: 20k0; Value: 20k; EIA_Code: E24; SizeX_mm: 3.2; SizeY_mm: 2.5; SizeZ_mm: 1.35; Value2: 0.5W; SizeArea_mm2: 8; AEC Qualified: N; VDC_V: 200V; AEC Category: Q200
R5 = CMP-0025899-5: RES, 1.0 k, 5%, 0.1 W, 0603; Manufacturer: Yageo; Power_W: 100mW; TempCo: 100 ppm/C; Value_Code: 1k00; Value: 1.0k; EIA_Code: E24; Res_ohm: 1k; SizeX_mm: 1.6; SizeY_mm: 0.8; SizeZ_mm: 1; Value2: 0.1W; SizeArea_mm2: 1.28; AEC Qualified: N; VDC_V: 75V; AEC Category: Q200; SizeAreaWB_mm2: 4.68
R6 R7 = CMP-0025885-5: RES, 0, 5%, 0.1 W, 0603; PartNumber: RC0603JR-070RL; Manufacturer: Yageo; Power_W: 100mW; VDC_V: 75V; AEC Qualified: N; SizeZ_mm: 1; AEC Category: Q200; EIA_Code: E24; SizeArea_mm2: 1.28; SizeAreaWB_mm2: 4.68; SizeX_mm: 1.6; SizeY_mm: 0.8; TempCo: 200 ppm/C; Value2: 0.1W; Value_Code: 0000
R8 R32 = CMP-0026935-3: RES, 47 k, 5%, 0.063 W, AEC-Q200 Grade 0, 0402; Manufacturer: Vishay-Dale; Power_W: 63mW; TempCo: 200 ppm/C; Value_Code: 47k0; Value: 47k; EIA_Code: E24; SizeX_mm: 1; SizeY_mm: 0.5; SizeZ_mm: 0.6; Value2: 0.063W; AEC Qualified: Y; VDC_V: 50V; AEC Category: Q200; AEC Grade: 0
R9 = CMP-0025875-3: RES, 100 k, 5%, 0.1 W, AEC-Q200 Grade 0, 0603; Manufacturer: Panasonic; Power_W: 100mW; TempCo: 200 ppm/C; U/M: EA; Value: 100k; EIA_Code: E24; SizeX_mm: 1.6; SizeY_mm: 0.8; SizeZ_mm: 1; Value2: 0.1W; SizeArea_mm2: 1.28; AEC Qualified: Y; VDC_V: 50V; AEC Grade: 0; AEC Category: Q200
R10 = CMP-0022941-4: RES, 249 k, 1%, 0.1 W, 0603; Manufacturer: Yageo; Power_W: 100mW; TempCo: 100 ppm/C; Value: 249k; EIA_Code: E96; SizeX_mm: 1.6; SizeY_mm: 0.8; SizeZ_mm: 1; Value2: 0.1W; SizeArea_mm2: 1.28; AEC Qualified: N; VDC_V: 75V; AEC Category: Q200; SizeAreaWB_mm2: 4.68
R11 = CMP-0023118-5: RES, 44.2 k, 1%, 0.1 W, 0603; Manufacturer: Yageo; Power_W: 100mW; TempCo: 100 ppm/C; Value_Code: 44k2; Value: 44.2k; EIA_Code: E96; SizeX_mm: 1.6; SizeY_mm: 0.8; SizeZ_mm: 1; Value2: 0.1W; SizeArea_mm2: 1.28; AEC Qualified: N; VDC_V: 75V; AEC Category: Q200; SizeAreaWB_mm2: 4.68
R12 = CMP-0022804-5: RES, 14.0 k, 1%, 0.1 W, 0603; Manufacturer: Yageo; Power_W: 100mW; TempCo: 100 ppm/C; Value_Code: 14k0; Value: 14.0k; EIA_Code: E96; Res_ohm: 14k; SizeX_mm: 1.6; SizeY_mm: 0.8; SizeZ_mm: 1; Value2: 0.1W; SizeArea_mm2: 1.28; AEC Qualified: N; VDC_V: 75V; AEC Category: Q200; SizeAreaWB_mm2: 4.68
R33 = CMP-0023155-5: RES, 4.99 k, 1%, 0.1 W, 0603; Manufacturer: Yageo; Power_W: 100mW; TempCo: 100 ppm/C; Value_Code: 4k99; Value: 4.99k; EIA_Code: E96; SizeX_mm: 1.6; SizeY_mm: 0.8; SizeZ_mm: 1; Value2: 0.1W; SizeArea_mm2: 1.28; AEC Qualified: N; VDC_V: 75V; AEC Category: Q200; SizeAreaWB_mm2: 4.68
R35-R44 = CMP-0025886-5: RES, 10 k, 5%, 0.1 W, 0603; Manufacturer: Yageo; Power_W: 100mW; TempCo: 100 ppm/C; Value_Code: 10k0; Value: 10k; EIA_Code: E24; SizeX_mm: 1.6; SizeY_mm: 0.8; SizeZ_mm: 1; Value2: 0.1W; SizeArea_mm2: 1.28; AEC Qualified: N; VDC_V: 75V; AEC Category: Q200; SizeAreaWB_mm2: 4.68
R74 = CMP-0022746-5: RES, 10.0 k, 1%, 0.1 W, 0603; Manufacturer: Yageo; Power_W: 100mW; TempCo: 100 ppm/C; Value_Code: 10k0; Value: 10.0k; EIA_Code: E96; Res_ohm: 10k; SizeX_mm: 1.6; SizeY_mm: 0.8; SizeZ_mm: 1; Value2: 0.1W; SizeArea_mm2: 1.28; AEC Qualified: N; VDC_V: 75V; AEC Category: Q200; SizeAreaWB_mm2: 4.68
R81 = CMP-0097568-1: 47 kOhms ±1% 0.125W, 1/8W Chip Resistor 0402 (1005 Metric) Automotive AEC-Q200 Thick Film; Manufacturer: Vishay Dale; AEC Grade: Grade 0; SizeZ_mm: 0.4mm; TempCo: 100ppm/°C; AEC Qualified: Yes; Power_W: 125mW; VDC_V: 75V
R82 = CMP-0023129-5: RES, 470, 1%, 0.1 W, 0603; Manufacturer: Yageo; Power_W: 100mW; TempCo: 100 ppm/C; Value_Code: 470R; Value: 470; SizeX_mm: 1.6; SizeY_mm: 0.8; SizeZ_mm: 1; Value2: 0.1W; SizeArea_mm2: 1.28; AEC Qualified: N; VDC_V: 75V; AEC Category: Q200; SizeAreaWB_mm2: 4.68
S1 = CMP-0097347-1: Tactile Switch SPST-NO Top Actuated Surface Mount; Manufacturer: Wurth Electronics; VDC_V: 12V; Electromechanical Life: 1000000Cycles; SizeZ_mm: 2.7mm; Coil Resistance_ohm: 100mΩ; Operating Force: 160gf; AEC Qualified: No; Contact Current Rating: 50mA
SH-J2-SH-J9 = CMP-0003761-2: as SH-J14 on sheet DRV81646DGQ_XDS110
TP8 = CMP-0055139-2: Test Point, Miniature, White, TH; Manufacturer: Keystone Electronics; ContactFinish: Silver; Green_REACh: Passed; CT: TRUE; Green_Lifecycle: Active; CNHeader: FALSE
TP9 TP11-TP15 = CMP-0055149-2: Test Point, Multipurpose, White, TH; Manufacturer: Keystone Electronics; ContactFinish: Silver; CT: TRUE; CNHeader: FALSE; Green_Lifecycle: Active; Green_REACh: Passed
TP10 = CMP-0055150-1: Test Point, Multipurpose, Orange, TH; Manufacturer: Keystone; CNHeader: FALSE; Green_Lifecycle: Active; Green_REACh: Passed; ContactFinish: Silver; CT: TRUE
TP33 = CMP-0055148-1: Test Point, Multipurpose, Black, TH; Manufacturer: Keystone; CNHeader: FALSE; Green_Lifecycle: Active; Green_REACh: Passed; ContactFinish: Silver; CT: TRUE
U1 = CMP-0093960-1: Mixed-Signal Microcontrollers With CAN-FD Interface LQFP64; Manufacturer: Texas Instruments; Number Of I2C Channels: 2; Frequency_Fixed: 80MHz; Number Of Cores: 1; Number Of Pwm Channels: 14; Data Bus Width: 32bits; Standoff Height: 0.05mm; SizeZ_mm: 1.6mm; Number Of I/Os: 60; Memory Type: FLASH; Min Supply Voltage: 1.62V; Number Of Adc Channels: 16; Memory Size: 128KBytes; TJmax_C: +130°C; Number Of Uart Channels: 4; Number Of Timers/Counters: 7; Max Supply Voltage: 3.6V; TaMin_C: -40°C; Core Architecture: ARM Cortex-M0+; Interface: I2C,SPI,UART,CAN,LIN,IrDA,SMBus; Ram Size: 32KBytes; AEC Qualified: No; TaMax_C: +125°C
Y1 = CMP-0098168-2: Crystal 40MHz ±10ppm (Tol) ±20ppm (Stability) 12pF FUND 40Ohm 4-Pin Mini-CSMD T/R; Manufacturer: Seiko Epson; SizeZ_mm: 0.6mm; AEC Qualified: No; Esr: 40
